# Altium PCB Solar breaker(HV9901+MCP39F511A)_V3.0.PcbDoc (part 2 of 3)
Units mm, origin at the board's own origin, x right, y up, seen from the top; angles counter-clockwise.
Board outline 92.89 x 56.75 mm, 4 copper layers (Component Side, Layer 2, Layer 3, Solder Side), stack 0.466 mm thick; 133 components, 95 nets, 366 pads, 141 vias.
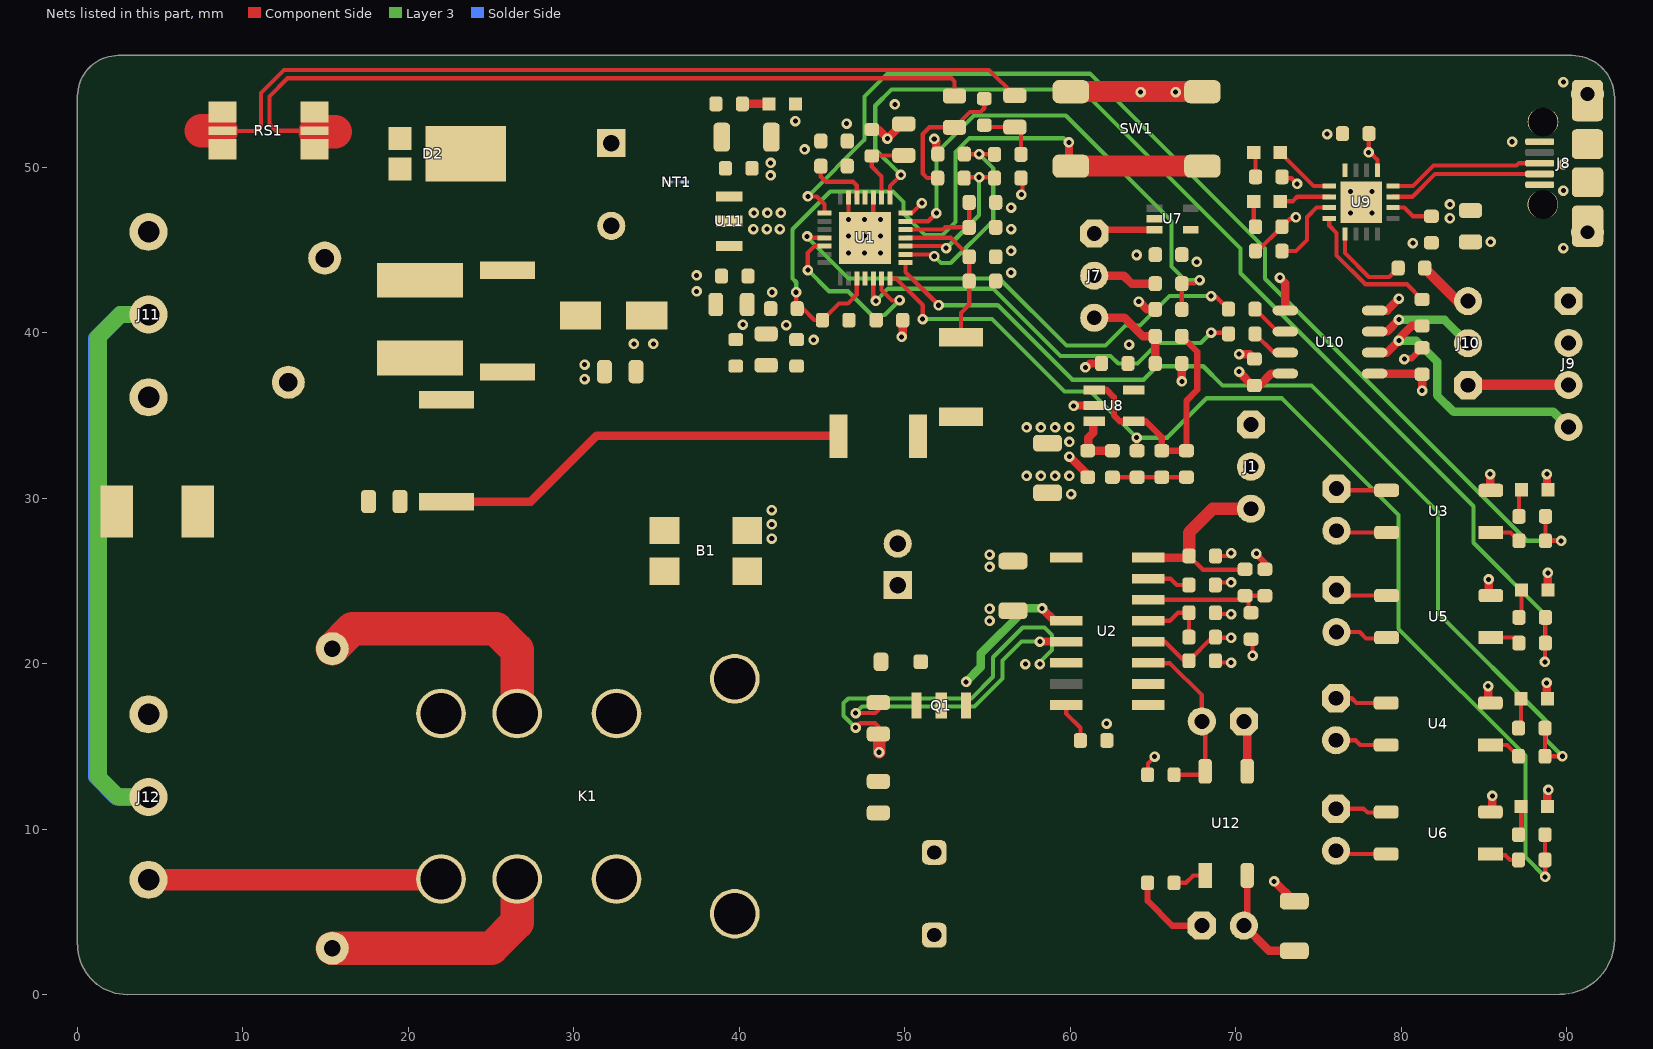
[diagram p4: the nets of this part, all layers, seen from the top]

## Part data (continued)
R1 R10: library part RSMT0568, Manufacturer 1="SPC Technology", Manufacturer Part Number 1=MC0603WGF4701T5E-TC, Operating Temperature="-55C to +155C", Package=0603, Power=1/16W, Supplier Part Number 1=58K4608, Temperature Coeffcient=100ppm/C, Tolerance=1%, Voltage=150V
R2 R3 R4 R5 R8 R9 R11 R12 R13 R14 R15 R16 R17 R18 R19 R20 R21 R22 R23 R24 R35 R36 R38 R41: library part RSMT0138, Manufacturer 1=Panasonic, Manufacturer 2=ROHM, Manufacturer 3="Stackpole Electronics Inc", Manufacturer 5=Vishay, Manufacturer 7=Yageo, Manufacturer 8="TE Connectivity", Manufacturer Part Number 1=ERJ-3EKF1001V, Manufacturer Part Number 2=MCR03EZPFX1001, Manufacturer Part Number 3=RMCF0603FT1K00, Manufacturer Part Number 4="RMCF 1/16 1K 1% R", Manufacturer Part Number 5=CRCW06031K00FKEA, Manufacturer Part Number 6=RMCF1/161.0K1%TR, Manufacturer Part Number 7=RC0603FR-071KL, Manufacturer Part Number 8=1622866-1, Operating Temperature="-55C to +155C", Package=0603, Power=1/10W, Supplier Part Number 1=P1.00KHCT-ND, Temperature Coeffcient=100ppm/C, Tolerance=1%, Voltage=75V
R6 R7: library part RSMT1084, Manufacturer 1="Vishay Dale", Manufacturer Part Number 1=CRCW2010499KFKEF, Package=2010, Power=3/4W, Supplier Part Number 1=541-499KACCT-ND, Temperature Coeffcient=100ppm/C, Tolerance=1%, Voltage=400V
R25 R28 R31 R32 R33 R34: library part RSMT0138, Manufacturer 1=Panasonic, Manufacturer 2=ROHM, Manufacturer 3="Stackpole Electronics Inc", Manufacturer 5=Vishay, Manufacturer 7=Yageo, Manufacturer 8="TE Connectivity", Manufacturer Part Number 1=ERJ-3EKF1001V, Manufacturer Part Number 2=MCR03EZPFX1001, Manufacturer Part Number 3=RMCF0603FT1K00, Manufacturer Part Number 4="RMCF 1/16 1K 1% R", Manufacturer Part Number 5=CRCW06031K00FKEA, Manufacturer Part Number 6=RMCF1/161.0K1%TR, Manufacturer Part Number 7=RC0603FR-071KL, Manufacturer Part Number 8=1622866-1, Operating Temperature="-55C to +155C", Package=0603, Power=1/10W, Supplier Part Number 1=P1.00KHCT-ND, Temperature Coeffcient=100ppm/C, Tolerance=5%, Voltage=75V
R26 R27 R29: library part RES1178, Manufacturer 1=Panasonic, Manufacturer Part Number 1=ERJ-3GEYJ472V, Operating Temperature="-55C to +155C", Package=0603, Power=1/10W, Supplier Part Number 1=P4.7KGCT-ND, Temperature Coeffcient=200ppm/C, Tolerance=1%, Voltage=75V
R30 R37: library part RSMT1143, Manufacturer 1="Vishay Dale", Manufacturer Part Number 1=CRCW2512402KFKEG, Operating Temperature="-55C to +155C", Package=2512, Power=2W, Supplier Part Number 1=541-402KAFCT-ND, Temperature Coeffcient=100ppm/C, Tolerance=1%, Voltage=500V
R39 R40: library part RES2320, Current=2A, Manufacturer 1="Panasonic Electronic Components", Manufacturer 2="Vishay Dale", Manufacturer Part Number 1=ERJ-8GEY0R00V, Manufacturer Part Number 2=CRCW12060000Z0EA, Operating Temperature="-55°C - 155?", Package=1206, Supplier Part Number 1=P0.0ECT-ND
RS1: library part RES1247, "Shunt", Manufacturer 1="Stackpole Electronics Inc", Manufacturer Part Number 1=CSNL2512FT2L00, Operating Temperature="-55C to +170C", Package=2512, Power=2W, Supplier Part Number 1=CSNL2512FT2L00CT-ND, Temperature Coeffcient=50ppm/C, Tolerance=1%, Voltage=200V
RS2: library part RSMT0248, Manufacturer 1="Stackpole Electronics Inc", Manufacturer Part Number 1=RMCF-1/10-39-1%, Operating Temperature="-55C to +155C", Package=0805, Power=1/8W, Temperature Coeffcient=100ppm/C, Tolerance=1%, Voltage=150V
SW1: library part SWITCH1046, "Switch", Manufacturer 1="Wurth Electronics Inc", Manufacturer 2="C&K Components", Manufacturer 3=SWITECH, Manufacturer Part Number 1=430182043816, Manufacturer Part Number 2="PTS645SM43SMTR92 LFS", Manufacturer Part Number 3=TS2A-043C-G9, Supplier Part Number 1=732-7004-1-ND
TP1 TP2: library part MISC0028, Manufacturer 1=Keystone, Manufacturer 2="FuZhou XiXiang", Manufacturer Part Number 1=5002, Manufacturer Part Number 2=CONN00189B01, Supplier Part Number 1=36-5002-ND
U1: library part MIC7556, "ADC", AntiTemper=No, Manufacturer 1="Microchip Technology Inc", Manufacturer Part Number 1=MCP39F511A-E/MQ, PackageType=QFN, PackageWidth=5x5x0.9mm, TempRange="-40C to +125C", VoltageRefDrift=7, VoltageRefTol=2
U2: "HV9901 Series 10 to 450V 1 mA 750 mW Universal Relay Driver - SOIC-16N", Package="SOIC-16 Microchip"
U3 U4 U5 U6 U12: library part IC1119, "Photocoupler", Manufacturer 1="Avago Technologies", Manufacturer Part Number 1=HCPL-181-00CE, Operating Temperature="-55C to +100C", Package=4-SMD, Supplier Part Number 1=516-1788-1-ND
U7: library part MIC3213, "MCP97XX", Manufacturer 1=Microchip, Manufacturer Part Number 1=MCP9700T-H/LT, MaxSupplyCurrent=6, PackageType=SC70, TempRange="-40C to +150C"
U8: library part MIC0507, "OPAMP", Manufacturer 1=Microchip, Manufacturer Part Number 1=MCP6021T-E/OT, PackageType=SOT-23, TempRange="-40C to +125C"
U9: library part MIC6971, Manufacturer 1="Microchip Technology", Manufacturer Part Number 1=MCP2221A-I/ML, Supplier Part Number 1=MCP2221A-I/ML-ND
U10: library part IC1047, "Bi-Directional Logic Gate Optocoupler (Fairchild)", Manufacturer 1="Fairchild Semiconductor", Operating Temperature="-40C to +110C", Package=SOIC-8, Supplier Part Number 1=FOD8012-ND
U11: library part MIC5969, "LDO", Manufacturer 1="Microchip Technology", Manufacturer Part Number 1=MCP1754ST-3302E/MB, PackageType=SOT-89, Supplier Part Number 1=MCP1754ST-3302E/MBCT-ND, TempRange="-40C to +125C"
Z1: library part DIODE1054, Manufacturer 1="Micro Commercial Co", Manufacturer Part Number 1=SMAZ5V6-TP, Operating Temperature="-65C to +150C", Package=DO-214AC(SMA), Power=3W, Reverse Current=5uA, Reverse Voltage=2V, Supplier Part Number 1=SMAZ5V6-TPMSTR-ND

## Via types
v1: diameter 0.635, hole 0.305, Component Side to Solder Side, tented both sides, 137 vias
v2: diameter 0.7, hole 0.3, Component Side to Solder Side, 4 vias

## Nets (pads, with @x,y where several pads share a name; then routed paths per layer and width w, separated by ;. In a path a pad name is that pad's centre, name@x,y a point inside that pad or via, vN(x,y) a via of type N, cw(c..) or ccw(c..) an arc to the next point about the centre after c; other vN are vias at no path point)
3.3A: C1.2 C31.2 C32.2 R1.2 R28.1 U1.11
3.3D: C8.2 C16.2 C18.2 C26.1 C29.2 C30.2 R10.1 R28.2 U1.25 U7.4 U8.5 U10.8 U11.3 | length 3.3
  Component Side w0.508: v1@70.194,37.637 C26.1@71.017,36.814 ; C26.1@71.119,36.814 71.429,36.814 72.139,37.524 U10.8@72.992,37.524
  other v1: 70.2,37.643 63.551,39.282 40.208,40.488 67.64,44.283 46.482,52.629 49.402,53.797
5VUSB: C22.1 C23.2 C25.1 J8.1 J9.1 R26.2 R27.2 R29.2 U9.16 U10.1 | length 8.2
  Component Side w0.254: R26.2@71.187,44.933 71.318,44.933 R27.2@72.787,46.403 72.787,46.413 73.1,46.726 73.11,46.726 73.287,46.902 73.562,46.902 v1(73.635,46.975) ; R29.2@72.795,49.342 72.795,49.331 73.376,49.331 v1(73.711,48.997)
  Component Side w0.508: U10.1@78.392,37.524 C22.1@81.223,37.524 ; v1(81.258,36.495) C22.1@81.258,37.484
  other v1: 82.935,46.916 82.935,47.753 75.514,52.005
AGND: C1.1 C2.1 C3.2 C4.1 C5.1 C6.1 C7.1 C31.1 C32.1 C36.1 NT1.1 R8.1 R9.1 SW1.1 SW1.2 U1.21 | length 14.7
  Component Side w0.254: U1.21@50.046,47.231 50.428,47.231 v1(51.028,47.831) ; v1(57.048,48.338) 57.101,48.391 C3.2@57.101,49.298
  Component Side w0.508: C7.1@48.002,52.28 48.391,52.28 v1(48.946,51.726) C6.1@49.885,52.665 ; v1(49.809,39.751) 49.809,39.785 49.87,39.846 C1.1@49.87,40.752 ; v1(51.777,51.714) 51.841,51.649 51.841,51.642 51.907,51.577 51.907,50.874 C2.1@51.994,50.787
  Component Side w1.27: SW1.1@60.033,54.563 SW1.2@67.983,54.563
  other v1: 44.49,39.56 42.832,40.462 41.975,42.443 56.418,43.631 56.418,44.941 56.418,46.252 56.418,47.562 64.247,54.534 66.367,54.534
EARTH: J11.2 J12.2 | length 67.6
  Layer 3 w1.016: J12.2@4.294,11.938 2.462,11.938 1.27,13.13 1.27,39.77 2.592,41.092 J11.2@4.294,41.092
  Solder Side w1.016: J12.2@4.294,11.938 2.373,11.938 1.143,13.168 1.143,39.643 2.592,41.092 J11.2@4.294,41.092
ENI: J13.2 R38.1 U2.11 U12.4 | length 10.7
  Component Side w0.254: U2.11@64.73,20.019 66.028,20.019 67.945,18.102 J13.2@67.945,16.51 68.148,16.307 U12.4@68.148,13.494 67.938,13.284 R38.1@66.268,13.284
EXT-MCU-IN: J2.1 R35.1 | length 5
  Component Side w0.381: R35.1@64.668,6.756 64.668,5.664 66.167,4.166 J2.1@67.945,4.166
EXT-RX: J9.4 R32.1 U10.2 | length 17.1
  Component Side w0.508: U10.2@78.392,38.794 79.129,38.794 v1(79.858,39.522) ; v1@79.858,39.649 80.616,40.408 R32.1@81.26,40.408
  Layer 3 w0.508: v1(79.858,39.522) 80.899,39.522 82.169,38.252 82.169,36.214 83.159,35.223 89.184,35.223 J9.4@90.104,34.303
EXT-TX: J9.3 J10.1 | length 6.1
  Component Side w0.254: J10.1@84.033,36.823 J10.1@84.053,36.843
  Component Side w0.635: J10.1@84.053,36.843 J9.3@90.104,36.843
GND: B1.4 C9.1 C10.1 C11.2 C12.2 C13.1 C35.2 J1.2 J13.1 R11.1 R14.1 R15.1 R39.2 R40.1 RS2.1 U2.6 U2.9 U12.3 | length 33.2
  Component Side w0.254: v1(47.022,16.128) 47.294,16.4 48.204,16.4 48.396,16.208 RS2.1@48.396,15.745 ; C12.2@68.765,20.175 68.874,20.066 v1(69.714,20.066) ; R14.1@68.764,23.074 68.84,22.999 v1(69.714,22.999) ; C10.1@68.764,24.75 68.918,24.904 v1(69.714,24.904) ; C11.2@68.776,26.506 69.539,26.506 v1(69.714,26.682) ; C13.1@70.917,21.476 71.017,21.376 v1(71.017,20.479)
  Component Side w0.381: v1(71.238,26.643) 71.238,26.619 71.755,26.102 R15.1@71.755,25.704
  Component Side w0.508: J13.1@70.485,16.51 70.688,16.307 U12.3@70.688,13.494 ; v1(72.309,6.844) 72.336,6.844 R39.2@73.533,5.647
  Component Side w0.762: v1(48.443,14.645) RS2.1@48.444,15.57
  Layer 3 w0.254: v1(47.022,16.128) 46.3,16.85 46.3,17.618 46.582,17.9 54.027,17.9 55.334,19.206 55.334,20.387 57.122,22.176 58.444,22.176 58.9,21.72 58.9,20.829 58.166,20.095 v1(58.166,19.964)
  other v1: 62.196,16.369 57.277,19.964 55.118,22.59 55.118,23.317 41.956,27.557 41.956,28.417 41.956,29.277 60.046,30.243 57.357,31.344 58.217,31.344 59.077,31.344 59.937,31.344
GND-EXT-MCU: J2.2 R39.1 U12.2 | length 6.8
  Component Side w0.381: J2.2@70.485,4.166 70.688,4.369 U12.2@70.688,7.194
  Component Side w0.508: J2.2@70.485,4.166 72.004,2.647 R39.1@73.533,2.647
GND-ISO: C22.2 C23.1 C24.2 C25.2 J8. J8.0 J8.5 J9.2 U9.13 U9.17 U10.4 | length 5.7
  Component Side w0.254: C25.2@78.05,52.026 78.029,52.005 v1(78.029,50.902) 78.105,50.902 78.562,50.444 U9.13@78.562,49.811 ; v1(80.188,38.405) v1@80.233,38.45 ; C24.2@81.797,45.415 C24.2@81.817,45.434 C24.2@81.867,45.484
  Component Side w0.381: v1@80.233,38.45 80.623,38.45 C22.2@81.26,39.087
  Component Side w0.508: U10.4@78.392,41.334 79.139,41.334 v1(79.858,42.053)
  other v1: 89.789,45.11 80.696,45.415 85.395,45.491 89.789,48.59 89.789,50.19 86.69,51.537 89.789,55.143
  other v2: 76.925,47.236 78.225,47.236 76.925,48.536 78.225,48.536
GNDB: C8.1 C16.1 C18.1 C19.1 C20.1 C21.1 C26.2 C27.1 C28.1 C29.1 C30.1 C37.2 FB4.2 LED1.2 LED2.2 LED3.2 LED4.2 LED7.2 NT1.2 R40.2 U1.24 U1.27 U1.29 U3.2 U4.2 U5.2 U6.2 U7.2 U8.2 U10.5 U11.2 Z1.1 | length 22.5
  Component Side w0.254: U1.27@46.596,48.181 v1(46.596,46.849) 46.596,46.731 U1.29@47.596,45.731 48.096,46.231 U1.24@48.096,48.181 ; v1@88.832,12.326 v1(88.883,12.377)
  Component Side w0.508: v1@59.944,32.512 59.944,32.505 C20.1@61.116,31.333 ; v1(60.198,35.573) 60.222,35.597 U8.2@61.434,35.597 ; v1(60.909,37.897) 60.944,37.897 61.184,38.137 C16.1@61.883,38.137 ; v1(64.135,41.874) 64.169,41.874 64.633,41.41 C21.1@65.137,41.41 ; v1@66.726,37.043 66.726,37.054 66.737,37.065 C19.1@66.737,38.137 ; v1(70.2,38.7) 70.833,38.7 C26.2@71.119,38.414 ; v1(72.669,43.332) 72.669,43.298 72.992,42.975 U10.5@72.992,41.334 ; U4.2@85.251,17.756 v1(85.251,18.642) ; U5.2@85.279,24.242 v1(85.279,25.092) ; U3.2@85.371,30.512 v1(85.371,31.452) ; U6.2@85.505,11.07 v1(85.505,12.011) ; LED2.2@88.78,17.932 v1(88.78,18.842) ; v1(88.798,31.452) 88.803,31.447 LED1.2@88.803,30.56 ; LED4.2@88.832,11.361 v1@88.832,12.326 ; LED3.2@88.859,24.443 v1(88.859,25.483)
  other v1: 59.937,32.512 59.937,33.397 57.357,34.282 58.217,34.282 59.077,34.282 59.937,34.282 66.737,37.054 33.628,39.317 34.8,39.317 37.419,42.489 37.419,43.464 64.008,44.694 46.596,44.817 47.569,44.817 48.534,44.817 46.596,45.833 47.569,45.833 48.534,45.833 42.443,46.253 40.844,46.259 41.657,46.259 47.569,46.849 48.534,46.849 40.883,47.244 41.696,47.244 42.508,47.244 41.891,49.505 41.891,50.267 43.942,51.081 43.383,52.786
L-IN: B1.1 F1.1 FB3.1 K1.6 MOV1.2
L-OUT: J12.3 K1.2 | length 18.2
  Component Side w1.3: J12.3@4.294,6.938 K1.2@21.925,6.938
  Layer 3 w1.016: K1.2@21.429,6.938 K1.2@21.798,6.569
MPU-RX1: R34.1 U1.4 | length 30.9
  Component Side w0.254: v1(44.094,45.822) 44.167,45.749 44.416,45.749 44.434,45.731 U1.4@45.146,45.731 ; v1(68.504,42.215) 68.577,42.142 68.839,42.142 R34.1@69.557,41.424
  Layer 3 w0.254: v1(44.094,45.822) 44.094,45.782 46.596,43.281 55.703,43.281 59.766,39.218 62.127,39.218 63.336,40.426 64.203,40.426 65.991,42.215 v1(68.504,42.215)
MPU-TX1: R31.1 U1.12 | length 25.7
  Component Side w0.254: U1.12@48.096,43.281 48.096,42.08 v1(48.255,41.922) ; v1(68.504,39.998) 69.487,39.998 R31.1@69.557,39.928
  Layer 3 w0.254: v1(48.255,41.922) 48.992,42.659 55.334,42.659 59.398,38.595 62.435,38.595 62.893,38.137 64.056,38.137 65.295,39.376 67.882,39.376 v1(68.504,39.998)
N-IN: B1.2 K1.5 MOV1.1 RS1.1 | length 1.2
  Component Side w2.032: 14.378,52.143 15.561,52.143
N-OUT: J12.1 K1.1 | length 0.9
  Layer 3 w1.016: J12.1@4.294,16.569 J12.1@4.294,16.938 J12.1@4.663,16.569
NetB1_3: B1.3 C9.2 C14.2 C35.1 D1.2 K1.7 U2.1
  other v1: 55.118,25.845 55.118,26.594
NetC2_2: C2.2 R2.1 U1.16 | length 12.7
  Component Side w0.254: U1.16@50.046,44.731 51.665,44.731 v1(51.777,44.619) ; C2.2@53.594,50.787 v1(54.487,50.787) R2.1@55.406,50.787
  Layer 3 w0.254: v1(51.777,44.619) 52.183,44.213 52.772,44.213 55.347,46.787 55.347,49.927 v1(54.487,50.787)
NetC3_1: C3.1 R5.1 U1.17 | length 9.5
  Component Side w0.254: U1.17@50.046,45.231 52.371,45.231 v1(52.498,45.104) ; R5.1@53.581,49.393 v1(54.487,49.393) 55.367,49.393 C3.1@55.418,49.342
  Layer 3 w0.254: v1(52.498,45.104) 54.487,47.093 v1(54.487,49.393)
NetC4_2: C4.2 R7.2 R8.2 U1.18 | length 9.4
  Component Side w0.254: U1.18@50.046,45.731 52.794,45.731 53.887,44.638 R8.2@53.887,44.588 C4.2@53.887,43.122 53.887,41.686 53.399,41.198 R7.2@53.399,39.723
NetC5_2: C5.2 R9.2 U1.19 | length 5.4
  Component Side w0.254: U1.19@50.046,46.231 52.291,46.231 52.426,46.366 C5.2@53.887,46.366 R9.2@53.887,47.87
NetC6_2: C6.2 C7.2 U1.23 | length 4.7
  Component Side w0.254: C7.2@48.002,50.68 48.002,50.042 48.596,49.449 U1.23@48.596,48.181 ; C7.2@48.002,50.714 C6.2@49.936,50.714
NetC10_2: C10.2 U2.15 | length 2.6
  Component Side w0.254: U2.15@64.697,25.131 66.052,25.131 66.433,24.75 C10.2@67.164,24.75
NetC13_2: C13.2 R13.1 R15.2 U2.14 | length 8.4
  Component Side w0.254: U2.14@64.697,23.861 70.266,23.861 R13.1@70.509,24.104 ; C13.2@70.917,23.076 70.76,23.233 70.76,23.853 R13.1@70.509,24.104 ; R15.2@71.755,24.104 R13.1@70.56,24.104 R13.1@70.509,24.104
NetC14_1: C14.1 K1.8 L1.2
NetC15_1: C15.1 C17.1 R23.1 R24.2 | length 4.5
  Component Side w0.254: R23.1@62.541,31.266 R24.2@64.033,31.266 C17.1@65.525,31.266 C15.1@67.017,31.266
NetC15_2: C15.2 C17.2 R22.1 U8.1 U8.4 | length 15.8
  Component Side w0.381: U8.1@61.434,36.547 62.184,36.547 62.634,36.097 62.634,35.006 62.992,34.647 U8.4@63.834,34.647 64.551,34.647 65.525,33.673 C17.2@65.525,32.866 C15.2@67.017,32.866 67.017,35.892 67.667,36.542 67.667,38.84 R22.1@66.734,39.773
NetC19_2: C19.2 J7.3 R22.2 | length 5.8
  Component Side w0.508: J7.3@61.443,40.902 63.267,40.902 64.393,39.776 R22.2@65.137,39.776 C19.2@65.137,38.137
NetC20_2: C20.2 R23.2 U8.3 | length 3.4
  Component Side w0.508: U8.3@61.387,34.647 61.387,33.955 61.071,33.639 61.071,32.866 R23.2@62.541,32.866
NetC21_2: C21.2 R25.2 U1.20 | length 31
  Component Side w0.254: U1.20@50.046,46.731 51.416,46.731 v1(51.906,47.22) ; C21.2@66.737,41.41 R25.2@66.737,42.966 67.501,42.966 67.715,43.18 v1(67.818,43.18)
  Layer 3 w0.254: v1(51.906,47.22) 51.906,50.855 54.171,53.12 59.724,53.12 66.105,46.739 66.105,43.998 66.922,43.18 v1(67.818,43.18)
NetC24_1: C24.1 U9.10 | length 2.5
  Component Side w0.254: U9.10@79.5,47.561 80.175,47.561 80.702,47.034 C24.1@81.817,47.034
NetC27_2: C27.2 C28.2 C37.1 D2.3 R36.2 U11.1
NetC33_1: C33.1 R30.2 R37.1
NetC33_2: C33.2 D2.1 D2.2 R30.1 Z1.2
NetC36_2: C36.2 R1.1 SW1.3 SW1.4 U1.10 | length 44.1
  Component Side w0.254: v1(43.434,42.443) 43.434,41.51 C36.2@43.491,41.453 43.839,41.453 44.525,40.768 45.018,40.768 46.02,41.769 46.553,41.769 47.096,42.312 U1.10@47.096,43.281
  Component Side w0.508: SW1.3@59.919,50.178 v1(59.919,51.499)
  Component Side w1.27: SW1.3@60.033,50.063 SW1.4@67.983,50.063
  Layer 3 w0.254: v1(43.434,42.443) v1@43.434,42.647 ; v1@43.612,42.469 v1@43.434,42.647 ; v1(59.919,51.499) 59.834,51.499 59.579,51.754 53.901,51.754 53.061,50.914 53.061,46.68 52.282,45.901 51.228,45.901 49.912,47.218 49.912,47.904 49.287,48.529 45.492,48.529 43.213,46.25 43.213,43.266 43.434,43.045 v1@43.434,42.647
NetD1_1: D1.1 L1.1 Q1.2
NetF1_2: F1.2 J11.3
NetFB1_2: FB1.2 R2.2 R41.1 | length 3.7
  Component Side w0.254: R41.1@54.8,52.542 54.92,52.422 FB1.2@56.645,52.422 57.018,52.049 R2.2@57.018,50.775
NetFB2_2: FB2.2 R5.2 R41.2 | length 8.3
  Component Side w0.254: R5.2@51.981,49.342 51.349,49.342 51.078,49.613 51.078,52.003 51.487,52.413 FB2.2@52.992,52.413 ; FB2.2@53.001,52.404 53.938,53.342 54.578,53.342 54.8,53.564 R41.2@54.8,54.142
NetFB3_2: FB3.2 R6.1 R37.2 | length 25.3
  Component Side w0.508: R37.2@22.3,29.791 27.391,29.791 31.382,33.782 R6.1@45.996,33.782
NetJ3_1: J3.1 U3.3 | length 3.6
  Component Side w0.254: J3.1@75.573,30.572 75.673,30.472 U3.3@79.111,30.472
NetJ3_2: J3.2 U3.4 | length 3.6
  Component Side w0.254: J3.2@75.573,28.032 75.673,27.932 U3.4@79.111,27.932
NetJ4_1: J4.1 U4.3 | length 3.1
  Component Side w0.254: J4.1@76.052,17.911 77.009,17.911 77.294,17.626 U4.3@79.081,17.626
NetJ4_2: J4.2 U4.4 | length 3.1
  Component Side w0.254: J4.2@76.052,15.371 77.237,15.371 77.522,15.086 U4.4@79.081,15.086
NetJ5_1: J5.1 U5.3 | length 3.7
  Component Side w0.254: J5.1@75.571,24.443 75.903,24.112 U5.3@79.109,24.112
NetJ5_2: J5.2 U5.4 | length 3.7
  Component Side w0.254: J5.2@75.571,21.903 77.487,21.903 77.876,21.514 79.051,21.514 U5.4@79.109,21.572
NetJ6_1: J6.1 U6.3 | length 3.1
  Component Side w0.254: J6.1@76.052,11.231 77.72,11.231 77.953,10.998 U6.3@79.048,10.998
NetJ6_2: J6.2 U6.4 | length 3.1
  Component Side w0.254: J6.2@76.052,8.691 76.252,8.491 U6.4@79.081,8.491
NetJ7_2: J7.2 R25.1 | length 3.9
  Component Side w0.508: J7.2@61.443,43.442 63.227,43.442 63.703,42.966 R25.1@65.137,42.966
NetJ10_2: J10.2 U10.3 | length 6.5
  Component Side w0.508: U10.3@78.41,40.082 79.152,40.082 v1(79.858,40.788)
  Layer 3 w0.508: v1@79.858,40.724 79.907,40.774 82.622,40.774 J10.2@84.033,39.363
NetJ10_3: J10.3 R33.1 | length 3.4
  Component Side w0.635: R33.1@81.451,43.869 83.442,41.878 J10.3@84.033,41.878
NetK1_3: K1.3 TP1.1 | length 16
  Component Side w2.032: TP1.1@15.4,20.9 16.6,22.1 25.3,22.1 26.572,20.828 K1.3@26.572,16.985
NetK1_4: K1.4 TP2.1 | length 14.5
  Component Side w2.032: TP2.1@15.4,2.8 25.025,2.8 26.572,4.347 K1.4@26.572,6.985
NetLED1_1: LED1.1 R3.1 | length 1.7
  Component Side w0.254: R3.1@87.111,28.902 87.111,30.352 LED1.1@87.261,30.502
NetLED2_1: LED2.1 R16.1 | length 1.8
  Component Side w0.254: R16.1@87.082,16.102 87.232,16.252 LED2.1@87.232,17.88
NetLED3_1: LED3.1 R18.1 | length 1.7
  Component Side w0.254: R18.1@87.109,22.793 87.259,22.943 LED3.1@87.259,24.443
NetLED4_1: LED4.1 R20.1 | length 1.8
  Component Side w0.254: R20.1@87.082,9.661 87.232,9.811 LED4.1@87.232,11.361
NetLED5_1: LED5.1 R27.1 | length 1.6
  Component Side w0.254: LED5.1@71.079,47.947 71.079,46.511 R27.1@71.187,46.403
NetLED6_1: LED6.1 R29.1 | length 1.6
  Component Side w0.254: LED6.1@71.079,50.886 71.195,50.77 R29.1@71.195,49.342
NetLED7_1: LED7.1 R36.1 | length 1.6
  Component Side w0.508: R36.1@40.181,53.824 LED7.1@41.791,53.824
NetQ1_1: Q1.1 U2.4 | length 8.7
  Component Side w0.508: v1(58.293,23.343) 59.044,22.591 U2.4@59.747,22.591
  Layer 3 w0.508: v1(53.697,18.9) 54.587,19.79 54.587,20.621 57.309,23.343 v1(58.293,23.343)
NetQ1_3: Q1.3 RS2.2 U2.5 | length 17
  Component Side w0.254: v1(47.022,17.01) 48.211,17.01 48.396,17.195 RS2.2@48.396,17.645
  Component Side w0.508: v1(58.166,21.336) U2.5@59.733,21.336
  Layer 3 w0.254: v1(47.022,17.01) 47.42,17.408 54.208,17.408 55.9,19.1 55.9,20.184 57.052,21.336 v1(58.166,21.336)
NetR3_2: R3.2 R4.2 U1.1 | length 67.1
  Component Side w0.254: v1@44.08,48.231 v1(44.137,48.231) 44.679,48.231 45.146,47.763 U1.1@45.146,47.231 ; R3.2@88.711,28.902 R4.2@88.711,27.424 v1(89.661,27.424)
  Layer 3 w0.254: v1(44.137,48.231) 47.569,51.662 47.569,54.275 48.946,55.651 61.185,55.651 71.755,45.081 71.755,43.259 87.59,27.424 v1(89.661,27.424)
NetR4_1: R4.1 U3.1 | length 1.9
  Component Side w0.254: U3.1@85.411,27.932 86.603,27.932 R4.1@87.111,27.424
NetR6_2: R6.2 R7.1
NetR10_2: R10.2 U1.26 | length 3.7
  Component Side w0.254: R10.2@44.92,50.064 44.92,49.441 45.237,49.124 46.863,49.124 47.096,48.891 U1.26@47.096,48.181
NetR11_2: R11.2 U2.8 | length 2.5
  Component Side w0.254: U2.8@59.747,17.511 59.747,16.988 60.608,16.128 R11.2@60.608,15.353
NetR12_1: R12.1 R14.2 U2.13 | length 4.1
  Component Side w0.254: U2.13@64.697,22.591 66.025,22.591 66.508,23.074 R14.2@67.164,23.074 R12.1@67.164,21.601
NetR16_2: R16.2 R17.2 U1.15 | length 60
  Component Side w0.254: U1.15@50.046,44.231 50.046,43.655 v1(52.045,41.656) ; R16.2@88.682,16.102 R17.2@88.682,14.402 v1(89.732,14.402)
  Layer 3 w0.254: v1(52.045,41.656) 55.619,41.656 60.115,37.16 64.434,37.16 65.247,37.973 68.03,37.973 69.203,36.8 74.579,36.8 82.22,29.159 82.22,23.054 88.727,16.547 88.727,15.407 v1(89.732,14.402)
NetR17_1: R17.1 U4.1 | length 2
  Component Side w0.254: U4.1@85.381,15.086 86.398,15.086 R17.1@87.082,14.402
NetR18_2: R18.2 R19.2 U1.22 | length 68.2
  Component Side w0.254: U1.22@49.096,48.181 49.096,48.867 v1(49.759,49.53) ; v1(88.682,20.112) 88.682,21.216 R19.2@88.709,21.243 R18.2@88.709,22.793
  Layer 3 w0.254: v1(49.759,49.53) 48.212,51.076 48.212,53.712 49.186,54.686 60.676,54.686 70.282,45.08 70.282,43.588 84.356,29.514 84.356,27.303 88.682,22.977 v1(88.682,20.112)
NetR19_1: R19.1 U5.1 | length 1.8
  Component Side w0.254: U5.1@85.409,21.572 86.78,21.572 R19.1@87.109,21.243
NetR20_2: R20.2 R21.2 R24.1 U1.14 | length 68
  Component Side w0.254: U1.14@49.096,43.281 49.462,43.281 51.079,41.663 v1(51.079,40.818) ; R24.1@64.008,32.891 v1(64.008,33.655) ; R20.2@88.682,9.661 R21.2@88.682,8.137 88.697,8.122 v1(88.697,7.112)
  Layer 3 w0.254: v1(51.079,40.818) 55.27,40.818 59.639,36.449 61.214,36.449 v1(64.008,33.655) 65.856,33.655 68.242,36.042 72.772,36.042 79.832,28.981 79.832,22.104 87.498,14.438 87.498,8.311 v1(88.697,7.112)
NetR21_1: R21.1 U6.1 | length 1.8
  Component Side w0.254: U6.1@85.381,8.417 86.305,8.417 86.585,8.137 R21.1@87.082,8.137
NetR26_1: R26.1 U9.3 | length 4.8
  Component Side w0.254: R26.1@72.787,44.933 73.633,44.933 74.308,45.608 74.308,46.998 74.316,46.998 74.879,47.561 U9.3@75.65,47.561
NetR31_2: R31.2 U10.7 | length 2.3
  Component Side w0.254: R31.2@71.157,39.928 72.291,38.794 U10.7@72.992,38.794
NetR34_2: R34.2 U10.6 | length 2.4
  Component Side w0.254: R34.2@71.157,41.424 72.517,40.064 U10.6@72.992,40.064
NetR35_2: R35.2 U12.1 | length 2.1
  Component Side w0.254: R35.2@66.268,6.756 66.994,6.756 67.432,7.194 U12.1@68.148,7.194
NetU1_5: U1.5 U1.13 | length 11.3
  Component Side w0.254: v1(44.137,43.778) 44.137,44.836 44.532,45.231 U1.5@45.146,45.231 ; U1.13@48.596,43.281 48.596,42.571 49.221,41.946 49.667,41.946 v1(49.682,41.961)
  Layer 3 w0.254: v1(44.137,43.778) 45.416,42.5 46.564,42.5 47.998,41.066 48.788,41.066 v1(49.682,41.961)
NetU2_10: U2.10
Neutral: FB4.1 J11.1 RS1.2 | length 1.2
  Component Side w2.032: 7.499,52.206 8.682,52.206
  other v1: 30.653,37.19 30.653,38.071
RX: R32.2 U9.4 | length 8.7
  Component Side w0.254: U9.4@75.65,46.911 75.65,46.46 76.081,46.028 76.081,44.67 77.826,42.926 80.342,42.926 R32.2@81.26,42.008
RX-LED: LED6.2 U9.1 | length 3.8
  Component Side w0.254: LED6.2@72.679,50.886 74.704,48.861 U9.1@75.65,48.861
SENSE+: FB1.1 RS1.4 | length 51.3
  Component Side w0.254: RS1.4@8.682,52.192 10.769,52.192 11.1,52.522 11.1,54.49 12.49,55.88 55.087,55.88 FB1.1@56.645,54.322
SENSE-: FB2.1 RS1.3 | length 47.4
  Component Side w0.254: RS1.3@14.319,52.206 12.003,52.206 11.608,52.601 11.608,54.28 12.7,55.372 52.811,55.372 53.001,55.182 FB2.1@53.001,54.304
TEMP-OUT: J7.1 U7.3 | length 3.7
  Component Side w0.381: J7.1@61.443,45.982 61.682,46.221 U7.3@65.083,46.221
TX: R33.2 U9.5 | length 5.2
  Component Side w0.254: U9.5@76.6,45.961 76.6,44.807 78.036,43.372 79.272,43.372 R33.2@79.81,43.91
TX-LED: LED5.2 U9.2 | length 3.1
  Component Side w0.254: LED5.2@72.679,47.947 73.447,47.947 73.711,48.211 U9.2@75.65,48.211
USB-N: J8.2 U9.11 | length 9.4
  Component Side w0.254: U9.11@79.5,48.211 80.667,48.211 82.047,49.591 J8.2@88.363,49.591
USB-P: J8.3 U9.12 | length 9.4
  Component Side w0.254: U9.12@79.5,48.861 80.706,48.861 81.941,50.096 86.97,50.096 87.115,50.241 J8.3@88.363,50.241
VCC: C12.1 J1.1 R12.2 R38.2 U2.12 | length 7.4
  Component Side w0.254: R38.2@64.685,13.284 64.685,13.966 v1(65.097,14.378) ; U2.12@64.697,21.321 65.712,21.321 66.858,20.175 C12.1@67.165,20.175 68.59,21.601 R12.2@68.764,21.601 68.801,21.565 v1(69.714,21.565)
VDD: C11.1 J1.3 R13.2 U2.16 | length 11.8
  Component Side w0.254: C11.1@67.176,26.506 68.007,25.675 R13.2@70.56,25.675
  Component Side w0.508: U2.16@64.697,26.401 C11.1@67.071,26.401
  Component Side w0.762: C11.1@67.176,26.506 67.176,27.919 68.618,29.362 J1.3@70.909,29.362
pads on no net: J8.4 NT1.0 U1.2 U1.3 U1.6 U1.7 U1.8 U1.9 U1.28 U2.7 U7.1 U7.5 U9.6 U9.7 U9.8 U9.9 U9.14 U9.15

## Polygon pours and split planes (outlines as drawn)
N-IN on Component Side "Component Side-GNDB" (solid, pour order 938): 16.993,49.099 16.993,53.407 16.425,53.975 13.462,53.975 13.462,43.688 14.224,42.926 16.242,42.926 16.993,43.677
GND-ISO on Component Side "Component Side-GND_ISO" (solid, remove dead copper, pour order 918): 74.93,54.799 74.93,44.923 77.61,42.244 77.61,39.694 79.226,38.078 81.775,38.078 92.6,38.078 92.6,55.101 91.106,56.595 76.726,56.595
L-IN on Component Side "Component Side-L-IN" (solid, pour order 1074): 6.35,27.483 6.626,27.206 36.4,27.206 36.4,28.9 33.09,28.902 32.8,28.611 18.589,28.611 18.5,28.7 18.109,29.091 18.109,31.4 18.1,31.409 18.1,33.3 13.125,38.275 12.141,38.275 11.074,37.208 11.074,31.877 10.236,31.039 6.536,31.039 6.274,30.777 6.274,27.559
Neutral on Component Side "Component Side-NetJ11_1" (solid, pour order 800): 0.762,45.339 0.762,52.705 2.032,53.975 9.525,53.975 9.553,53.947 9.553,46.266 7.447,44.16 1.941,44.16
GND on Component Side "Component Side-GND" (solid, pour order 954): 58.79,19.75 60.731,19.75 60.731,20.422 58.11,20.422 57.627,20.904 57.627,22.88 57.627,23.526 57.368,23.785 55.64,23.785 54.916,23.785 54.635,23.504 54.635,21.772 56.388,20.019 56.388,16.016 59.857,12.548 62.052,12.548 62.992,13.487 64.282,14.777 64.592,15.088 65.354,15.088 65.837,15.57 65.837,17.907 63.687,17.907 63.686,17.738 62.687,16.739 61.931,16.739 61.646,16.454 61.646,14.529 60.671,14.529 58.191,17.009 58.191,19.152
GND on Component Side "Component Side-GND 2" (solid, pour order 1112): 39.815,29.62 50.046,29.62 51.3,28.366 51.3,27 50.752,26.452 50.616,26.316 48.983,26.316 48.093,27.206 39.503,27.206 39.498,29.301
GNDB on Component Side "Component Side-GNDB 1" (solid, remove dead copper, pour order 1110): 38.79,40.939 38.804,40.925 39.359,41.479 39.359,44.05 39.218,44.19 38.436,44.19 38.117,44.509 38.117,45.83 38.631,46.344 40.201,46.344 40.901,45.644 42.761,45.644 43.332,46.215 43.332,49.809 44.323,50.8 44.649,51.126 45.209,51.126 45.314,51.231 45.314,54 44.856,54.458 44.806,54.508 42.977,54.508 42.813,54.345 42.813,53.188 42.569,52.959 40.538,52.959 40.056,52.477 40.056,49.301 40.711,48.646 40.711,47.634 40.166,47.084 38.591,47.084 37.839,47.084 34.882,47.084 34.524,47.442 34.041,47.442 31.592,47.442 31.318,47.168 31.318,45.568 31.318,44.605 33,42.923 33,40.157 33.2,39.958 33.2,36.975 33.432,36.743 36.619,36.743 37.9,38.023 37.9,39.475 37.9,40.049
NetC33_2 on Component Side "Component Side-NetC33_2" (solid, pour order 1106): 17.8,42.4 18.1,42.1 23.4,42.1 23.413,42.113 26.904,42.113 29,40.017 31.7,40.017 31.7,40.829 31.7,42.367 30.898,43.169 30.103,43.169 28.764,44.509 26.6,46.672 25.254,48.018 24.464,48.018 24.389,48.018 23.024,48.018 20.582,48.018 20.293,48.307 20.293,53.907 19.8,54.4 18.3,54.4 17.8,53.9 17.8,47.334
N-IN on Component Side "Component Side-N-IN" (solid, pour order 1096): 30.898,16.234 30.898,24.852 32.498,26.452 36.378,26.452 36.378,22.767 34.4,20.79 34.4,16.4 33.22,15.22 31.912,15.22
N-OUT on Component Side "Component Side-N-OUT" (solid, pour order 1092): 2.02,18.5 8.4,18.5 9.6,17.3 19.258,17.3 20.658,18.7 22.432,18.7 23.6,17.532 23.6,16 22.515,14.915 22.038,14.438 7.9,14.438 7.038,15.3 1.9,15.3 1.1,16.1 1.1,17.58
NetQ1_1 on Component Side "Component Side-NetQ1_1" (solid, pour order 1090): 53.3,16.604 53.3,19.068 53.532,19.3 54,19.3 54.2,19.1 54.2,16.657 54.147,16.604
NetC14_1 on Component Side "Component Side-NetC14_1" (solid, pour order 1088): 39.343,1.657 52.232,1.657 52.7,2.125 52.7,4.122 52.422,4.4 50.9,4.4 49.1,6.2 49.1,11.521 49.021,11.6 47.777,11.6 45.146,8.969 39.969,8.969 38,7 38,3
NetD1_1 on Component Side "Component Side-NetD1_1" (solid, pour order 1086): 50.659,20.787 52.077,20.787 52.647,20.216 52.647,16.596 53.097,16.15 53.097,8.833 53.1,8.137 52.463,7.5 52.275,7.5 50.9,7.5 50.5,7.9 50.4,8 50.4,13.273 51.297,14.17 51.297,16.15 51.842,16.695 51.842,18.265 50.934,19.173 50.299,19.797 50.299,20.427
NetQ1_3 on Component Side "Component Side-NetQ1_3" (solid, pour order 1084): 47.895,18.842 50.586,18.842 51.1,18.328 51.1,16.621 51.079,16.6 49.954,16.6 49.354,17.2 47.7,17.2 47.5,17.4 47.5,18.447
NetB1_3 on Component Side "Component Side-NetB1_3" (solid, pour order 1082): 39.531,26.506 43.306,26.506 44.137,25.675 51.871,25.675 51.994,25.675 53.405,27.086 54.958,27.086 60.521,27.086 60.776,26.831 60.776,26.13 60.681,26.035 57.76,26.035 57.302,25.578 55.322,25.578 55.246,25.502 54.471,25.502 51.77,22.8 49.909,22.8 49.044,21.936 49.044,19.622 48.859,19.437 46.882,19.437 45.8,18.355 45.8,15.332 47.532,13.6 48.821,13.6 49.2,13.221 49.2,12.5 49.044,12.344 44.962,12.344 39.837,17.47 38.81,17.47 38.117,18.163 38.117,20.187 39.531,21.601
no net on Component Side "Component Side-No Net 6" (solid, pour order 1080): 54.1,25.4
no net on Component Side "Component Side-No Net 7" (solid, pour order 1078): 53.8,25.4
NetFB3_2 on Component Side "Component Side-NetFB3_2" (solid, pour order 1070): 19.4,31.3 23.439,31.3 24.076,30.662 24.076,29.118 24,29.041 19.134,29.041 18.9,29.275 18.9,30.8
NetC33_1 on Component Side "Component Side-NetC33_1" (solid, pour order 1062): 18.023,39.56 26.22,39.56 27.9,37.88 27.9,36.309 26.791,35.2 20.293,35.2 18.023,37.47
Neutral on Component Side "Component Side-Neutral" (solid, pour order 1060): 30.151,38.133 30.465,38.447 32.111,38.447 32.3,38.258 32.3,37.043 32.092,36.835 30.379,36.835 30.151,37.062
NetC27_2 on Component Side "Component Side-NetC27_2" (solid, pour order 1056): 26.6,49.725 33.858,49.725 35.692,47.891 40.233,47.891 40.233,48.551 39.548,49.236 39.548,52.793 39.218,53.123 39.218,54.095 38.804,54.508 23.647,54.508 21.708,54.508 21,53.8 21,49.175 21.375,48.8 25.6,48.8 25.675,48.8
3.3D on Component Side "Component Side-3.3D 2" (solid, pour order 1022): 47.863,53.391 48.514,53.391 49.712,53.391 49.876,53.554 49.886,53.564 49.886,54.407 49.53,54.762 46.485,54.762 45.695,53.972 45.695,53.01 45.695,49.814 46.052,49.456 47.077,49.456 47.435,49.098 47.435,47.727 47.803,47.727 47.803,49.63 47.352,50.08 47.352,52.88
GND on Component Side "Component Side-GND 1" (solid, pour order 958): 56.972,31.699 60.071,31.699 60.3,31.471 60.3,30.766 60.521,30.545 60.521,30.277 60.521,29.71 60.376,29.566 57.597,29.566 57.055,29.566 56.674,29.947 56.674,31.401
GNDB on Component Side "Component Side-GNDB 4" (solid, pour order 964): 59.817,33.02 60.147,33.02 60.4,33.272 60.4,33.603 60.4,34.368 60.071,34.696 57.252,34.696 56.998,34.442 56.998,33.133 57.695,32.436 59.233,32.436
3.3A on Component Side "Component Side-3.3A" (solid, pour order 930): 39.427,38.659 44.681,38.659 46.126,40.104 46.126,41.173 46.261,41.308 46.617,41.308 47.422,42.113 47.422,43.747 47.785,43.747 47.803,43.729 47.803,41.537 48.006,41.334 48.787,41.334 48.969,41.153 48.969,40.651 45.632,37.338 39.497,37.338 39.218,37.617 39.218,38.449
AGND on Component Side "Component Side-AGND 1" (solid, pour order 928): 40.719,39.38 40.719,40.2 41.407,40.888 41.407,43.342 41.55,43.485 42.356,43.485 42.508,43.332 42.508,41.308 43.354,40.462 44.058,40.462 44.922,39.599 44.922,39.268 44.643,38.989 41.11,38.989
3.3D on Component Side "Component Side-3.3D 3" (solid, pour order 926): 38.438,45.644 38.438,44.838 38.657,44.619 39.201,44.619 39.722,44.098 39.722,41.068 39.218,40.564 39.218,39.23 39.361,39.087 40.272,39.087 40.431,39.246 40.431,40.18 41.122,40.871 41.122,44.885 40.362,45.644
GNDB on Component Side "Component Side-GNDB 2" (solid, pour order 740): 64.584,47.137 64.604,47.117 66.444,47.117 66.642,46.914 66.642,45.627 65.737,44.722 65.737,44.322 65.506,44.091 63.9,44.091 63.483,44.509 63.483,44.929 64.345,45.791 65.737,45.791 65.737,46.64 64.584,46.64
NetR6_2 on Component Side "Component Side-NetR6_2" (solid, pour order 888): 50.174,35.204 50.453,35.484 54.716,35.484 54.798,35.402 54.798,34.366 52.791,32.36 50.158,32.36
5VUSB on Component Side "Component Side-5VUSB 1" (solid, pour order 754): 89.281,49.088 89.239,49.13 83.636,49.13 82.448,47.942 82.448,46.552 82.666,46.334 84.762,46.334 85.294,46.866 89.116,46.866 89.281,47.032
NetF1_2 on Component Side "Component Side-NetF1_2" (solid, pour order 806): 5.588,37.338 1.27,37.338 0.889,36.957 0.889,27.94 1.27,27.559 3.429,27.559 3.429,30.861 6.096,33.528 6.096,36.83
no net on Component Side "Component Side-No Net 5" (solid, pour order 802): 13.335,43.778
AGND on Component Side "Component Side-AGND" (solid, pour order 768): 56.726,49.868 56.536,49.678 56.536,48.872 56.101,48.438 55.244,48.438 55.067,48.261 55.067,42.291 55.296,42.062 57.506,42.062 58.217,42.774 58.217,49.563 57.912,49.868
5VUSB on Component Side "Component Side-5VUSB" (solid, pour order 756): 75.525,49.418 76.865,49.418 76.868,52.542 74.589,52.542 74.016,51.968 74.016,50.927
3.3D on Component Side "Component Side-3.3D" (solid, pour order 746): 66.808,46.482 67.884,46.482 67.983,46.384 67.983,44.125 67.768,43.911 66.655,43.911 66.203,44.363 66.203,45.021 66.485,45.304 66.808,45.304
3.3D on Component Side "Component Side-3.3D 1" (solid, pour order 744): 62.964,36.481 62.964,39.207 63.381,39.624 63.853,39.624 64.505,38.972 64.505,37.773 64.505,37.247 64.77,36.982 64.77,36.218 64.493,35.941 63.504,35.941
